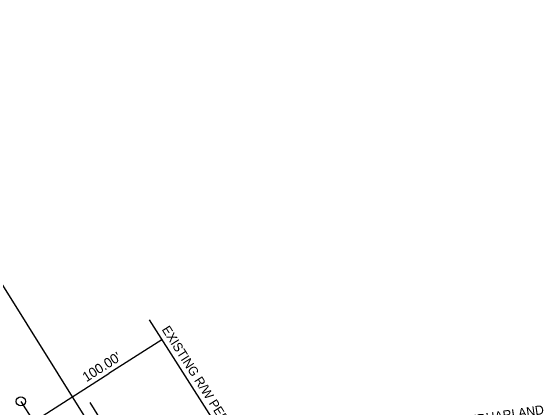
# Model space of a CAD drawing. Extents: x 1645945 to 2447332, y 713118 to 970361.
# Drawn here: x 1646155.6 to 1646330.7, y 969715.1 to 969845.6 of the extents above; entities that cross this region are included whole.
import ezdxf

# ---------------------------------------------------------------- set-up
doc = ezdxf.new("R2010")
doc.units = 0
for name, color, linetype in [('Exist Horizontal Alignment', 7, 'Continuous'), ('Exist Horizontal Alignment Station Label', 7, 'Continuous'), ('Exist Property Owner Text', 7, 'Continuous'), ('Exist Right of Way Line', 7, 'Continuous'), ('Exist Right of Way Line Text', 7, 'Continuous'), ('Exist Right of Way Width CELL', 7, 'Continuous'), ('Exist Structure Minor Pipes RCP 15 Inch', 7, 'Continuous'), ('Exist Utilities Sanitary Sewer UG Line', 7, 'Continuous')]:
    doc.layers.add(name, color=color, linetype=linetype)

msp = doc.modelspace()

# ---------------------------------------------------------------- linework, layer by layer
at = {"layer": 'Exist Horizontal Alignment'}
msp.add_line((1646158.92, 969717.09), (1646248.52, 969576.48), dxfattribs=at)
at = {"layer": 'Exist Horizontal Alignment Station Label'}
msp.add_circle((1646158.92, 969717.09), 1.5, dxfattribs=at)
at = {"layer": 'Exist Right of Way Line'}
msp.add_line((1646201.09, 969743.96), (1646290.69, 969603.35), dxfattribs=at)
at = {"layer": 'Exist Right of Way Width CELL'}
for p in [(1646205.29, 969737.37), (1646120.95, 969683.63)]:
    msp.add_line(p, (1646187.89, 969726.29), dxfattribs=at)
at = {"layer": 'Exist Structure Minor Pipes RCP 15 Inch'}
msp.add_line((1646181.59, 969716.71), (1646223.1, 969650.57), dxfattribs=at)
at = {"layer": 'Exist Utilities Sanitary Sewer UG Line'}
msp.add_line((1646096.45, 969845.65), (1646327.92, 969475.04), dxfattribs=at)

# ---------------------------------------------------------------- texts
at = {"layer": 'Exist Property Owner Text'}
msp.add_text('PARESHKUMAR N. CHAUDHARI AND ', height=3, rotation=8.183, dxfattribs=at).set_placement((1646261.13, 969702.9))
at = {"layer": 'Exist Right of Way Line Text'}
msp.add_text('EXISTING R/W PER STATE PROJ. #8.1640701', height=3, rotation=302.506, dxfattribs=at).set_placement((1646205.15, 969740.75))
at = {"layer": 'Exist Right of Way Width CELL'}
msp.add_text("100.00'", height=3.2, rotation=32.506, dxfattribs=at).set_placement((1646180.48, 969723.37))

doc.saveas('drawing.dxf')
